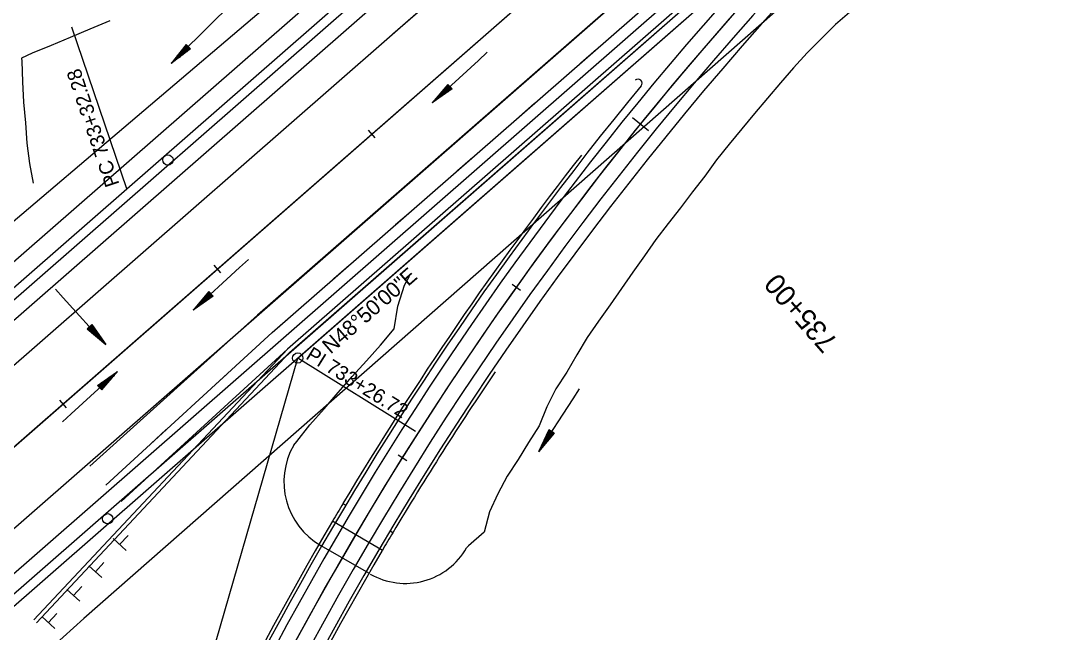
# Model space of a CAD drawing. Extents: x 1300404 to 1323571, y 234004 to 252077.
# Drawn here: x 1311569 to 1312081, y 241590 to 241888 of the extents above; entities that cross this region are included whole.
import ezdxf

# ---------------------------------------------------------------- set-up
doc = ezdxf.new("R2010")
doc.units = 0
for name, color, linetype in [('R_Barrel', 7, 'Continuous'), ('R_Bridge', 7, 'Continuous'), ('R_Const Limits', 7, 'Continuous'), ('R_Draft', 7, 'Continuous'), ('R_Flooplain', 7, 'Continuous'), ('R_Flow Arrows', 7, 'Continuous'), ('R_Guardrail', 7, 'Continuous'), ('R_Horz Alg Annot', 7, 'Continuous'), ('R_Horz Alg Annot Leader', 7, 'Continuous'), ('R_Horz Alg Major Ticks', 7, 'Continuous'), ('R_Horz Alg Minor Ticks', 7, 'Continuous'), ('R_Horz Alg Station Annot', 7, 'Continuous'), ('R_Horz Alg Tangents', 7, 'Continuous'), ('R_Horz Alg Tangents Text', 7, 'Continuous'), ('R_Lane Edge', 7, 'Continuous'), ('R_Proposed', 7, 'Continuous'), ('R_Shoulder', 7, 'Continuous'), ('R_Temp Barrier Wall', 7, 'Continuous'), ('R_Temp Travel Lane', 7, 'Continuous'), ('R_Temp Travel Stripe', 7, 'Continuous')]:
    doc.layers.add(name, color=color, linetype=linetype)

msp = doc.modelspace()

# ---------------------------------------------------------------- linework, layer by layer
at = {"layer": 'R_Barrel'}
for p, q in [((1311620.2, 241630.14), (1311613.88, 241635.97)), ((1311617.06, 241633.04), (1311621.13, 241637.45)), ((1311605.27, 241619.79), (1311609.34, 241624.2)), ((1311608.42, 241616.89), (1311602.09, 241622.72)), ((1311597.68, 241605.33), (1311591.36, 241611.17)), ((1311594.54, 241608.23), (1311598.61, 241612.64)), ((1311582.36, 241595), (1311586.43, 241599.41)), ((1311585.51, 241592.1), (1311579.18, 241597.94))]:
    msp.add_line(p, q, dxfattribs=at)
for centre in [(1311640.6, 241820.59), (1311611.22, 241645.6)]:
    msp.add_circle(centre, 2.5, dxfattribs=at)
at = {"layer": 'R_Bridge'}
for p, q in [((1311725.94, 241653.08), (1311727.3, 241652.26)), ((1311745.12, 241630.19), (1311720.84, 241644.47)), ((1311750.22, 241638.8), (1311748.86, 241639.61))]:
    msp.add_line(p, q, dxfattribs=at)
for centre, radius, start, end in [((1313143.25, 240808.04), 1650.1, 149.19568, 149.5429), ((1313143.24, 240808.04), 1650.1, 149.54256, 158.82191), ((1313143.25, 240808.04), 1621.94, 149.18961, 149.54287), ((1313143.24, 240808.04), 1621.94, 149.54252, 158.82195)]:
    msp.add_arc(centre, radius, start, end, dxfattribs=at)
at = {"layer": 'R_Const Limits'}
msp.add_line((1311738.61, 241619.01), (1311714.22, 241633.09), dxfattribs=at)
msp.add_line((1311738.61, 241619.01), (1311714.22, 241633.09), dxfattribs=at)
for points in [[(1311992.27, 241909.18), (1311965.99, 241886.62), (1311965.99, 241886.62), (1311965.99, 241886.62), (1311965.99, 241886.62), (1311959.06, 241879.73), (1311952.18, 241872.8), (1311945.61, 241865.57), (1311939.24, 241858.18), (1311932.94, 241850.73), (1311926.61, 241843.3), (1311920.36, 241835.81), (1311914.16, 241828.27), (1311908.09, 241820.63), (1311902.33, 241812.74), (1311896.33, 241805.05), (1311890.41, 241797.3), (1311884.42, 241789.6), (1311878.52, 241781.84), (1311872.88, 241773.88), (1311867.31, 241765.87), (1311861.67, 241757.92), (1311856.14, 241749.89), (1311850.58, 241741.89), (1311844.96, 241733.93), (1311840, 241725.51), (1311835.13, 241717.04), (1311829.64, 241709.01), (1311825.3, 241700.19), (1311821.6, 241690.97), (1311816.44, 241682.74), (1311811.31, 241674.5), (1311806.03, 241666.36), (1311801.44, 241657.77), (1311797.29, 241648.93), (1311794.74, 241639.11), (1311787.05, 241632.46), (1311786.21, 241631.43), (1311786.21, 241631.43)], [(1311612.23, 241888.49), (1311602.53, 241884.31), (1311592.9, 241880.27), (1311583.67, 241876.36), (1311574.36, 241872.69), (1311569.23, 241870.24)], [(1311569.23, 241870.24), (1311569.31, 241868.71), (1311569.66, 241858.71), (1311570.14, 241848.73), (1311571.11, 241838.76), (1311571.82, 241828.78), (1311573.15, 241818.84), (1311574.87, 241809.28), (1311574.87, 241809.28), (1311574.87, 241809.28)], [(1311701.9, 241681.46), (1311703.4, 241683.31), (1311709.85, 241691.43), (1311716.7, 241699.28), (1311723.55, 241707.1), (1311730.41, 241714.9), (1311737.4, 241722.58), (1311744.27, 241730.33), (1311750.83, 241738.25), (1311752.75, 241749.31), (1311755.88, 241759.59), (1311758.29, 241763.87)], [(1311701.9, 241681.46), (1311703.4, 241683.31), (1311709.85, 241691.43), (1311716.7, 241699.28), (1311723.55, 241707.1), (1311730.41, 241714.9), (1311737.4, 241722.58), (1311744.27, 241730.33), (1311750.83, 241738.25), (1311752.75, 241749.31), (1311755.88, 241759.59), (1311758.29, 241763.87)]]:
    msp.add_lwpolyline(points, dxfattribs=at)
for centre, radius, start, end in [((1311733.02, 241663.64), 35.86, 150.212, 239.9997), ((1311733.02, 241663.64), 35.86, 150.212, 239.9997), ((1311756.39, 241648.34), 34.28, 239.9997, 330.4542), ((1311756.39, 241648.34), 34.28, 239.9997, 330.4542)]:
    msp.add_arc(centre, radius, start, end, dxfattribs=at)
at = {"layer": 'R_Draft'}
for p, q in [((1308396.96, 238971.92), (1312368.36, 242444.53)), ((1308407.83, 238959.5), (1312379.22, 242432.11)), ((1308447.32, 238914.33), (1312418.71, 242386.94)), ((1308458.18, 238901.91), (1312429.57, 242374.52)), ((1309184.47, 239689.08), (1312131.36, 242265.86)), ((1309037.78, 239548.19), (1312137.61, 242258.71)), ((1309193.69, 239678.54), (1312140.58, 242255.32)), ((1309413.86, 239721.62), (1312065.67, 242040.38)), ((1309410.89, 239725), (1311987.97, 241978.41)), ((1309410.89, 239725), (1311987.97, 241978.41))]:
    msp.add_line(p, q, dxfattribs=at)
at = {"layer": 'R_Flooplain'}
for p, q in [((1311459.52, 241700.85), (1312470.12, 242559.7)), ((1312629.3, 242500.87), (1311599.52, 241597.01)), ((1311599.52, 241597.01), (1311574.18, 241574.09))]:
    msp.add_line(p, q, dxfattribs=at)
at = {"layer": 'R_Flow Arrows'}
for p, q in [((1311649.45, 241876.98), (1311642.25, 241867.58)), ((1311651.61, 241874.84), (1311642.25, 241867.58)), ((1311651.61, 241874.84), (1311649.45, 241876.98)), ((1311777.07, 241857.47), (1311769.44, 241848.41)), ((1311779.12, 241855.23), (1311769.44, 241848.41)), ((1311779.12, 241855.23), (1311777.07, 241857.47)), ((1311660.55, 241756.38), (1311652.92, 241747.32)), ((1311662.61, 241754.14), (1311652.92, 241747.32)), ((1311662.61, 241754.14), (1311660.55, 241756.38)), ((1311603.45, 241740.27), (1311601.21, 241738.2)), ((1311601.21, 241738.2), (1311610.3, 241730.61)), ((1311603.45, 241740.27), (1311610.3, 241730.61)), ((1311606.32, 241710.66), (1311616.01, 241717.48)), ((1311608.38, 241708.42), (1311616.01, 241717.48)), ((1311606.32, 241710.66), (1311608.38, 241708.42)), ((1311826.36, 241689.02), (1311821.32, 241678.3)), ((1311828.92, 241687.39), (1311821.32, 241678.3)), ((1311828.92, 241687.39), (1311826.36, 241689.02))]:
    msp.add_line(p, q, dxfattribs=at)
for points in [[(1311668.12, 241893.32), (1311664.02, 241889.26), (1311642.15, 241867.68)], [(1311650.32, 241876.13), (1311645.94, 241871.72), (1311643.69, 241869.46)], [(1311650.75, 241875.7), (1311646.37, 241871.29), (1311644.12, 241869.04)], [(1311650.1, 241876.34), (1311645.72, 241871.93), (1311645.13, 241871.34)], [(1311650.96, 241875.49), (1311646.58, 241871.07), (1311645.99, 241870.48)], [(1311649.88, 241876.56), (1311646.57, 241873.22)], [(1311651.18, 241875.27), (1311647.87, 241871.94)], [(1311649.67, 241876.77), (1311648.01, 241875.1)], [(1311651.39, 241875.06), (1311649.74, 241873.39)], [(1311796.31, 241873.09), (1311792.08, 241869.18), (1311769.44, 241848.41)], [(1311777.89, 241856.58), (1311773.31, 241852.37), (1311770.96, 241850.23)], [(1311778.3, 241856.13), (1311773.72, 241851.92), (1311771.37, 241849.78)], [(1311777.68, 241856.8), (1311773.1, 241852.6), (1311772.49, 241852.04)], [(1311778.51, 241855.9), (1311773.92, 241851.7), (1311773.31, 241851.14)], [(1311777.48, 241857.02), (1311774.01, 241853.85)], [(1311778.71, 241855.68), (1311775.25, 241852.5)], [(1311777.27, 241857.25), (1311775.54, 241855.66)], [(1311778.92, 241855.46), (1311777.18, 241853.87)], [(1311679.8, 241772.01), (1311675.56, 241768.09), (1311652.92, 241747.32)], [(1311585.7, 241757.55), (1311589.58, 241753.29), (1311610.19, 241730.51)], [(1311661.37, 241755.49), (1311656.79, 241751.28), (1311654.44, 241749.14)], [(1311661.78, 241755.04), (1311657.2, 241750.83), (1311654.85, 241748.69)], [(1311661.17, 241755.71), (1311656.59, 241751.51), (1311655.97, 241750.95)], [(1311661.99, 241754.82), (1311657.41, 241750.61), (1311656.79, 241750.05)], [(1311660.96, 241755.94), (1311657.5, 241752.76)], [(1311662.2, 241754.59), (1311658.73, 241751.41)], [(1311660.76, 241756.16), (1311659.03, 241754.57)], [(1311662.4, 241754.37), (1311660.67, 241752.78)], [(1311601.44, 241738.41), (1311603.03, 241736.68)], [(1311601.66, 241738.62), (1311604.85, 241735.16)], [(1311601.88, 241738.82), (1311606.1, 241734.26), (1311606.67, 241733.64)], [(1311602.11, 241739.03), (1311606.33, 241734.46), (1311608.48, 241732.12)], [(1311602.55, 241739.44), (1311606.77, 241734.88), (1311608.93, 241732.53)], [(1311602.78, 241739.65), (1311607, 241735.08), (1311607.56, 241734.47)], [(1311603, 241739.85), (1311606.19, 241736.4)], [(1311603.22, 241740.06), (1311604.82, 241738.33)], [(1311589.13, 241692.8), (1311593.37, 241696.71), (1311616.01, 241717.48)], [(1311607.14, 241709.76), (1311611.72, 241713.97), (1311614.08, 241716.11)], [(1311606.53, 241710.43), (1311608.26, 241712.02)], [(1311606.73, 241710.21), (1311610.2, 241713.39)], [(1311606.94, 241709.99), (1311611.52, 241714.19), (1311612.14, 241714.75)], [(1311607.56, 241709.31), (1311612.14, 241713.52), (1311614.49, 241715.66)], [(1311607.76, 241709.09), (1311612.34, 241713.29), (1311612.96, 241713.85)], [(1311607.97, 241708.87), (1311611.43, 241712.04)], [(1311608.17, 241708.64), (1311609.9, 241710.23)], [(1311841.14, 241708.94), (1311838, 241704.1), (1311821.2, 241678.38)], [(1311827.39, 241688.37), (1311824.04, 241683.13), (1311822.32, 241680.45)], [(1311827.9, 241688.04), (1311824.55, 241682.8), (1311822.83, 241680.12)], [(1311827.13, 241688.53), (1311823.78, 241683.29), (1311823.34, 241682.59)], [(1311826.87, 241688.69), (1311824.34, 241684.73)], [(1311828.16, 241687.88), (1311824.81, 241682.64), (1311824.36, 241681.93)], [(1311826.62, 241688.86), (1311825.35, 241686.88)], [(1311828.41, 241687.71), (1311825.88, 241683.75)], [(1311828.67, 241687.55), (1311827.4, 241685.57)]]:
    msp.add_lwpolyline(points, dxfattribs=at)
at = {"layer": 'R_Guardrail'}
for centre, radius, start, end in [((1313143.24, 240808.04), 1650.1, 142.0428, 149.19537), ((1313143.24, 240808.04), 1650.1, 142.0428, 149.19537), ((1313143.25, 240808.04), 1621.94, 145.90788, 149.18929), ((1313143.25, 240808.04), 1621.94, 145.90788, 149.18929)]:
    msp.add_arc(centre, radius, start, end, dxfattribs=at)
at = {"layer": 'R_Horz Alg Annot Leader'}
for points in [[(1311593.52, 241885.54), (1311620.39, 241806.61)], [(1311593.52, 241885.54), (1311620.39, 241806.61)], [(1311761.36, 241688.22), (1311703.85, 241724)], [(1311761.36, 241688.22), (1311703.85, 241724)]]:
    msp.add_lwpolyline(points, dxfattribs=at)
at = {"layer": 'R_Horz Alg Major Ticks'}
msp.add_lwpolyline([(1311867.07, 241841.29), (1311874.84, 241835)], dxfattribs=at)
msp.add_lwpolyline([(1311867.07, 241841.29), (1311874.84, 241835)], dxfattribs=at)
at = {"layer": 'R_Horz Alg Minor Ticks'}
for points in [[(1311738.24, 241835.1), (1311741.53, 241831.34)], [(1311738.24, 241835.1), (1311741.53, 241831.34)], [(1311662.96, 241769.28), (1311666.25, 241765.51)], [(1311662.96, 241769.28), (1311666.25, 241765.51)], [(1311808.41, 241760), (1311812.48, 241757.1)], [(1311808.41, 241760), (1311812.48, 241757.1)], [(1311587.68, 241703.45), (1311590.97, 241699.69)], [(1311587.68, 241703.45), (1311590.97, 241699.69)], [(1311752.78, 241676.73), (1311757.02, 241674.09)], [(1311752.78, 241676.73), (1311757.02, 241674.09)]]:
    msp.add_lwpolyline(points, dxfattribs=at)
at = {"layer": 'R_Horz Alg Tangents'}
for p, q in [((1311703.85, 241724), (1312065.67, 242040.38)), ((1311703.85, 241724), (1312065.67, 242040.38)), ((1311570.49, 241262.23), (1311703.85, 241724)), ((1311570.49, 241262.23), (1311703.85, 241724))]:
    msp.add_line(p, q, dxfattribs=at)
at = {"layer": 'R_Lane Edge'}
for radius, start in [(1629.52, 131.16667), (1644.52, 136.45181)]:
    msp.add_arc((1313143.24, 240808.04), radius, start, 163.89183, dxfattribs=at)
at = {"layer": 'R_Proposed'}
for p, q in [((1308427.57, 238936.91), (1312793.8, 242754.77)), ((1308427.57, 238936.91), (1312793.8, 242754.77)), ((1309180.37, 239595.16), (1312398.96, 242409.52)), ((1309180.37, 239595.16), (1312398.96, 242409.52))]:
    msp.add_line(p, q, dxfattribs=at)
msp.add_circle((1311703.85, 241724), 2.5, dxfattribs=at)
msp.add_circle((1311703.85, 241724), 2.5, dxfattribs=at)
for end in [163.89183, 163.89183, 163.04191, 163.04191]:
    msp.add_arc((1313143.24, 240808.04), 1637.02, 131.16667, end, dxfattribs=at)
at = {"layer": 'R_Shoulder'}
for centre, radius, start, end in [((1313143.24, 240808.04), 1623.52, 131.16667, 163.89183), ((1311869.76, 241858.01), 2, 320.4948, 130.9731), ((1313143.24, 240808.04), 1648.52, 140.49476, 163.89183)]:
    msp.add_arc(centre, radius, start, end, dxfattribs=at)
at = {"layer": 'R_Temp Barrier Wall'}
for p, q in [((1312162.13, 242133.19), (1311698.81, 241728.32)), ((1311699.92, 241726.65), (1312163.45, 242131.69)), ((1311698.81, 241728.32), (1311575.14, 241596.3)), ((1311699.92, 241726.65), (1311576.46, 241594.79))]:
    msp.add_line(p, q, dxfattribs=at)
at = {"layer": 'R_Temp Travel Lane'}
for p, q in [((1312147.66, 242149.76), (1311684.33, 241744.89)), ((1311684.33, 241744.89), (1311602.53, 241671.33)), ((1311698.81, 241728.32), (1311617.72, 241653.95))]:
    msp.add_line(p, q, dxfattribs=at)
at = {"layer": 'R_Temp Travel Stripe'}
for p, q in [((1311691.47, 241736.52), (1312154.9, 242141.47)), ((1311750.21, 241882.15), (1311833.5, 241954.02)), ((1311610.28, 241662.05), (1311691.47, 241736.52))]:
    msp.add_line(p, q, dxfattribs=at)
for points in [[(1311841.95, 241868.02), (1311849.48, 241874.6)], [(1311811.83, 241841.7), (1311819.36, 241848.28)], [(1311781.71, 241815.38), (1311789.24, 241821.96)], [(1311751.59, 241789.06), (1311759.12, 241795.64)], [(1311721.47, 241762.73), (1311729, 241769.31)], [(1311691.35, 241736.41), (1311691.47, 241736.52), (1311698.88, 241742.99)], [(1311661.87, 241709.37), (1311669.24, 241716.13)], [(1311632.39, 241682.33), (1311639.76, 241689.09)]]:
    msp.add_lwpolyline(points, dxfattribs=at)

# ---------------------------------------------------------------- texts
at = {"layer": 'R_Horz Alg Annot'}
for s, rotation, p in [('PC 733+32.28', 108.7991, (1311617.01, 241808.85)), ('PC 733+32.28', 108.7991, (1311617.01, 241808.85)), ('PI 733+26.72', 328.1141, (1311707.35, 241723.92)), ('PI 733+26.72', 328.1141, (1311707.35, 241723.92))]:
    msp.add_text(s, height=7, rotation=rotation, dxfattribs=at).set_placement(p)
at = {"layer": 'R_Horz Alg Station Annot'}
msp.add_text('735+00', height=10, rotation=131.1667, dxfattribs=at).set_placement((1311967.67, 241732.23))
msp.add_text('735+00', height=10, rotation=131.1667, dxfattribs=at).set_placement((1311967.67, 241732.23))
at = {"layer": 'R_Horz Alg Tangents Text'}
msp.add_text('N48%%d50\'00"E', height=7.5, rotation=41.1667, dxfattribs=at).set_placement((1311719.89, 241725.64))

doc.saveas('drawing.dxf')
